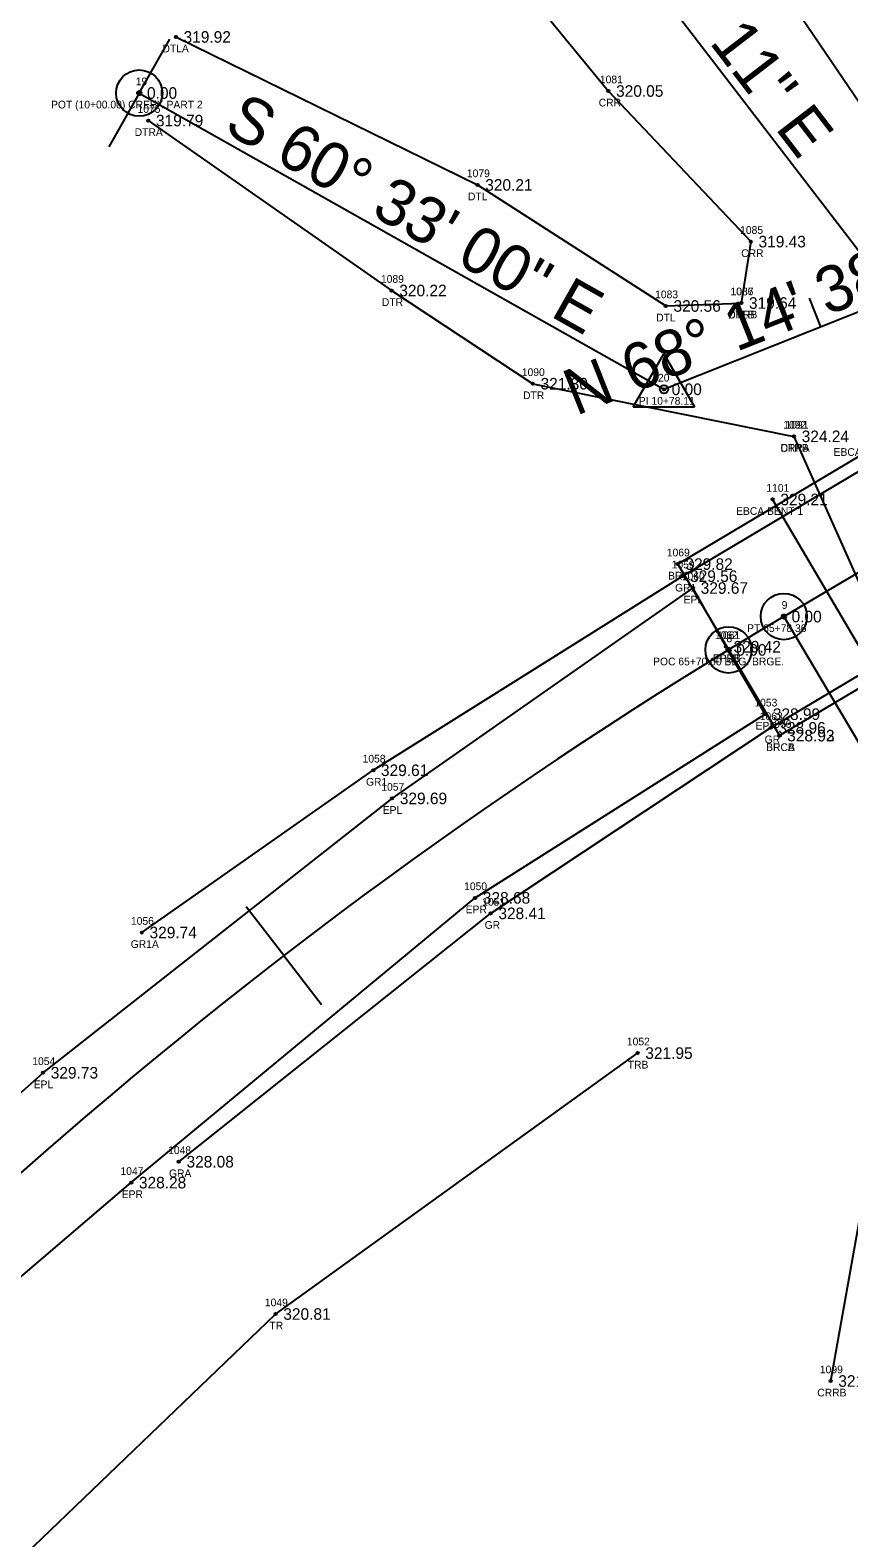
# Model space of a CAD drawing. Extents: x 2231119 to 2232595, y 1035731 to 1037094.
# Drawn here: x 2231451.3 to 2231557.4, y 1036309.5 to 1036504.9 of the extents above; entities that cross this region are included whole.
import ezdxf

# ---------------------------------------------------------------- set-up
doc = ezdxf.new("R2010")
doc.units = 0
for name, color, linetype in [('RD_EX_Bridge', 7, 'Continuous'), ('RD_EX_Bridge_txCode', 7, 'Continuous'), ('RD_EX_GuardRail', 7, 'Continuous'), ('RD_EX_GuardRail_txCode', 7, 'Continuous'), ('RD_EX_H2O', 7, 'Continuous'), ('RD_EX_H2O_txCode', 7, 'Continuous'), ('RD_EX_Road', 7, 'Continuous'), ('RD_EX_Road_txCode', 7, 'Continuous'), ('RD_EX_TX_Bridge_ELEV', 7, 'Continuous'), ('RD_EX_TX_GuardRail_ELEV', 7, 'Continuous'), ('RD_EX_TX_H2O_ELEV', 7, 'Continuous'), ('RD_EX_TX_Road_ELEV', 7, 'Continuous'), ('RD_EX_TX_VEG_ELEV', 7, 'Continuous'), ('RD_EX_VEG', 7, 'Continuous'), ('RD_EX_VEG_txCode', 7, 'Continuous'), ('RD_HC_Cl', 7, 'Continuous'), ('RD_HC_Data', 7, 'Continuous'), ('RD_HC_Data_Tic', 7, 'Continuous'), ('RD_HC_Survey_ELEV', 7, 'Continuous'), ('RD_HC_txCode', 7, 'Continuous'), ('RD_SMD_Locator', 7, 'Continuous')]:
    doc.layers.add(name, color=color, linetype=linetype)

msp = doc.modelspace()

# ---------------------------------------------------------------- linework, layer by layer
at = {"layer": 'RD_EX_Bridge'}
msp.add_line((2231547.53, 1036444.05), (2231561.63, 1036420.05), dxfattribs=at)
msp.add_lwpolyline([(2231548.42, 1036413.44), (2231612.8, 1036451.71), (2231599.65, 1036473.99), (2231535.22, 1036435.67), (2231548.41, 1036413.44)], dxfattribs=at)
at = {"layer": 'RD_EX_GuardRail'}
for points in [[(2231465.75, 1036387.92), (2231495.75, 1036408.95), (2231535.82, 1036434.11), (2231600.8, 1036472.75), (2231670.25, 1036516.04)], [(2231470.54, 1036358.21), (2231510.97, 1036390.4), (2231547.27, 1036414.45), (2231612.03, 1036453.05), (2231683.18, 1036493.79)]]:
    msp.add_lwpolyline(points, dxfattribs=at)
at = {"layer": 'RD_EX_H2O'}
for points in [[(2231513.64, 1036552.7), (2231545.27, 1036515.4), (2231572.49, 1036475.34)], [(2231494.58, 1036535.55), (2231526.23, 1036496.99), (2231544.7, 1036477.47), (2231543.46, 1036469.51)], [(2231470.16, 1036504), (2231509.27, 1036484.82), (2231533.67, 1036469.13), (2231543.46, 1036469.51)], [(2231466.58, 1036493.16), (2231498.13, 1036471.13), (2231516.44, 1036459.05), (2231550.29, 1036452.23)], [(2231550.29, 1036452.23), (2231565.49, 1036418.12), (2231564.98, 1036385.4), (2231555.04, 1036329.79)]]:
    msp.add_lwpolyline(points, dxfattribs=at)
at = {"layer": 'RD_EX_Road'}
for points in [[(2231158.42, 1035748.11), (2231188.37, 1035851.38), (2231216.59, 1035946.92), (2231244.77, 1036040.72), (2231278.59, 1036133.31), (2231299.55, 1036179.73), (2231323.11, 1036221.2), (2231350.7, 1036262.3), (2231381.59, 1036299.29), (2231415.97, 1036336.9), (2231452.94, 1036369.74), (2231498.19, 1036405.3), (2231537.2, 1036432.57), (2231541.46, 1036424.96)], [(2231176.43, 1035742.89), (2231206.61, 1035845.83), (2231234.19, 1035940.65), (2231261.92, 1036033.75), (2231294.68, 1036125.28), (2231316.11, 1036171.75), (2231338.19, 1036211.09), (2231363.83, 1036252.38), (2231394.08, 1036289.28), (2231427.67, 1036324.2), (2231464.37, 1036355.5), (2231508.96, 1036392.41), (2231546.55, 1036416.22), (2231541.46, 1036424.96)]]:
    msp.add_lwpolyline(points, dxfattribs=at)
at = {"layer": 'RD_EX_VEG'}
msp.add_lwpolyline([(2231211.01, 1035732.98), (2231244.87, 1035834.47), (2231267.87, 1035928.24), (2231283.13, 1036029.08), (2231316.25, 1036116.26), (2231338.15, 1036162.94), (2231357.98, 1036198.54), (2231413.07, 1036272.2), (2231445.22, 1036302.16), (2231483.09, 1036338.47), (2231530.02, 1036372.29)], dxfattribs=at)
at = {"layer": 'RD_HC_Cl'}
for p, q in [((2231548.98, 1036428.87), (2232281.06, 1036863.23)), ((2231504.54, 1036546.81), (2231563.32, 1036470.25)), ((2231465.42, 1036496.73), (2231533.44, 1036458.33)), ((2231533.44, 1036458.33), (2231563.32, 1036470.25))]:
    msp.add_line(p, q, dxfattribs=at)
msp.add_arc((2231880.38, 1035870.33), 649.46, 120.68197, 163.7355, dxfattribs=at)
at = {"layer": 'RD_HC_Data'}
for p, q in [((2231529.46, 1036456.04), (2231533.44, 1036462.92)), ((2231533.44, 1036462.92), (2231537.41, 1036456.04)), ((2231529.46, 1036456.04), (2231537.41, 1036456.04)), ((2231548.98, 1036428.87), (2231608.15, 1036329.15))]:
    msp.add_line(p, q, dxfattribs=at)
for centre, radius in [((2231465.42, 1036496.73), 3), ((2231465.42, 1036496.73), 0.282), ((2231533.44, 1036458.33), 0.529), ((2231548.98, 1036428.87), 3), ((2231541.82, 1036424.55), 3), ((2231548.98, 1036428.87), 0.282), ((2231541.82, 1036424.55), 0.282)]:
    msp.add_circle(centre, radius, dxfattribs=at)
at = {"layer": 'RD_HC_Data_Tic'}
for p, q in [((2231465.42, 1036496.73), (2231469.36, 1036503.7)), ((2231465.42, 1036496.73), (2231461.49, 1036489.76)), ((2231553.77, 1036466.44), (2231552.29, 1036470.16)), ((2231484.16, 1036384.92), (2231479.28, 1036391.26)), ((2231484.16, 1036384.92), (2231489.04, 1036378.58))]:
    msp.add_line(p, q, dxfattribs=at)
at = {"layer": 'RD_SMD_Locator'}
for centre in [(2231470.16, 1036504), (2231465.42, 1036496.73), (2231526.23, 1036496.99), (2231466.58, 1036493.16), (2231509.27, 1036484.82), (2231544.7, 1036477.47), (2231498.13, 1036471.13), (2231533.67, 1036469.13), (2231543.46, 1036469.51), (2231543.46, 1036469.51), (2231516.44, 1036459.05), (2231533.44, 1036458.33), (2231550.29, 1036452.23), (2231550.29, 1036452.23), (2231547.53, 1036444.05), (2231535.22, 1036435.67), (2231535.82, 1036434.11), (2231537.2, 1036432.57), (2231548.98, 1036428.87), (2231541.46, 1036424.96), (2231541.46, 1036424.96), (2231541.82, 1036424.55), (2231546.55, 1036416.22), (2231547.27, 1036414.45), (2231548.41, 1036413.44), (2231548.42, 1036413.44), (2231495.75, 1036408.95), (2231498.19, 1036405.3), (2231508.96, 1036392.41), (2231510.97, 1036390.4), (2231465.75, 1036387.92), (2231530.02, 1036372.29), (2231452.94, 1036369.74), (2231470.54, 1036358.21), (2231464.37, 1036355.5), (2231483.09, 1036338.47), (2231555.04, 1036329.79)]:
    msp.add_circle(centre, 0.15, dxfattribs=at)

# ---------------------------------------------------------------- texts
at = {"layer": 'RD_EX_Bridge_txCode'}
for s, p in [('EBCA BENT 2', (2231555.43, 1036449.7)), ('1101', (2231546.71, 1036445.05)), ('EBCA BENT 1', (2231542.79, 1036442.05)), ('1069', (2231533.81, 1036436.67)), ('BRC', (2231533.97, 1036433.67)), ('1070', (2231546.99, 1036414.44)), ('1066', (2231546.98, 1036414.44)), ('BRCA', (2231546.68, 1036411.44)), ('BRCB', (2231546.69, 1036411.44))]:
    msp.add_text(s, height=1, dxfattribs=at).set_placement(p)
at = {"layer": 'RD_EX_GuardRail_txCode'}
for s, p in [('1059', (2231534.44, 1036435.11)), ('GR1', (2231534.88, 1036432.11)), ('1063', (2231545.86, 1036415.45)), ('GR', (2231546.49, 1036412.45)), ('1058', (2231494.37, 1036409.95)), ('GR1', (2231494.81, 1036406.95)), ('1051', (2231509.87, 1036391.4)), ('1056', (2231464.34, 1036388.92)), ('GR', (2231510.19, 1036388.4)), ('GR1A', (2231464.31, 1036385.92)), ('1048', (2231469.16, 1036359.21)), ('GRA', (2231469.27, 1036356.21))]:
    msp.add_text(s, height=1, dxfattribs=at).set_placement(p)
at = {"layer": 'RD_EX_H2O_txCode'}
for s, p in [('DTLA', (2231468.42, 1036502)), ('1081', (2231525.13, 1036497.99)), ('CRR', (2231524.98, 1036494.99)), ('1075', (2231465.19, 1036494.16)), ('DTRA', (2231464.82, 1036491.16)), ('1079', (2231507.89, 1036485.82)), ('DTL', (2231508.03, 1036482.82)), ('1085', (2231543.31, 1036478.47)), ('CRR', (2231543.45, 1036475.47)), ('1089', (2231496.75, 1036472.13)), ('1083', (2231532.29, 1036470.13)), ('1086', (2231542.05, 1036470.51)), ('1087', (2231542.08, 1036470.51)), ('DTR', (2231496.87, 1036469.13)), ('CRRB', (2231541.74, 1036467.51)), ('DTLB', (2231541.75, 1036467.51)), ('DTL', (2231532.43, 1036467.13)), ('1090', (2231515.01, 1036460.05)), ('DTR', (2231515.17, 1036457.05)), ('1092', (2231548.91, 1036453.23)), ('1091', (2231549.19, 1036453.23)), ('CRRA', (2231548.55, 1036450.23)), ('DTRB', (2231548.55, 1036450.23)), ('1099', (2231553.65, 1036330.79)), ('CRRB', (2231553.31, 1036327.79))]:
    msp.add_text(s, height=1, dxfattribs=at).set_placement(p)
at = {"layer": 'RD_EX_Road_txCode'}
for s, p in [('1060', (2231535.75, 1036433.57)), ('EPL', (2231535.99, 1036430.57)), ('1062', (2231540.05, 1036425.96)), ('1061', (2231540.33, 1036425.96)), ('EPRB', (2231539.76, 1036422.96)), ('EPLB', (2231539.78, 1036422.96)), ('1053', (2231545.16, 1036417.22)), ('EPR', (2231545.32, 1036414.22)), ('1057', (2231496.8, 1036406.3)), ('EPL', (2231496.98, 1036403.3)), ('1050', (2231507.53, 1036393.41)), ('EPR', (2231507.73, 1036390.41)), ('1054', (2231451.55, 1036370.74)), ('EPL', (2231451.73, 1036367.74)), ('1047', (2231462.98, 1036356.5)), ('EPR', (2231463.14, 1036353.5))]:
    msp.add_text(s, height=1, dxfattribs=at).set_placement(p)
at = {"layer": 'RD_EX_TX_Bridge_ELEV'}
for s, p in [('329.21', (2231548.53, 1036443.3)), ('329.82', (2231536.22, 1036434.92)), ('328.93', (2231549.42, 1036412.69)), ('328.92', (2231549.41, 1036412.69))]:
    msp.add_text(s, height=1.5, dxfattribs=at).set_placement(p)
at = {"layer": 'RD_EX_TX_GuardRail_ELEV'}
for s, p in [('329.56', (2231536.82, 1036433.36)), ('328.96', (2231548.27, 1036413.7)), ('329.61', (2231496.75, 1036408.2)), ('328.41', (2231511.97, 1036389.65)), ('329.74', (2231466.75, 1036387.17)), ('328.08', (2231471.54, 1036357.46))]:
    msp.add_text(s, height=1.5, dxfattribs=at).set_placement(p)
at = {"layer": 'RD_EX_TX_H2O_ELEV'}
for s, p in [('319.92', (2231471.16, 1036503.25)), ('320.05', (2231527.23, 1036496.24)), ('319.79', (2231467.58, 1036492.41)), ('320.21', (2231510.27, 1036484.07)), ('319.43', (2231545.7, 1036476.72)), ('320.22', (2231499.13, 1036470.38)), ('319.64', (2231544.46, 1036468.76)), ('319.64', (2231544.46, 1036468.76)), ('320.56', (2231534.67, 1036468.38)), ('321.30', (2231517.44, 1036458.3)), ('324.24', (2231551.29, 1036451.48)), ('324.24', (2231551.29, 1036451.48)), ('321.00', (2231556.04, 1036329.04))]:
    msp.add_text(s, height=1.5, dxfattribs=at).set_placement(p)
at = {"layer": 'RD_EX_TX_Road_ELEV'}
for s, p in [('329.67', (2231538.2, 1036431.82)), ('329.42', (2231542.46, 1036424.21)), ('329.42', (2231542.46, 1036424.21)), ('328.99', (2231547.55, 1036415.47)), ('329.69', (2231499.19, 1036404.55)), ('328.68', (2231509.96, 1036391.66)), ('329.73', (2231453.94, 1036368.99)), ('328.28', (2231465.37, 1036354.75))]:
    msp.add_text(s, height=1.5, dxfattribs=at).set_placement(p)
at = {"layer": 'RD_EX_TX_VEG_ELEV'}
for s, p in [('321.95', (2231531.02, 1036371.54)), ('320.81', (2231484.09, 1036337.72))]:
    msp.add_text(s, height=1.5, dxfattribs=at).set_placement(p)
at = {"layer": 'RD_EX_VEG_txCode'}
for s, p in [('1052', (2231528.63, 1036373.29)), ('TRB', (2231528.75, 1036370.29)), ('1049', (2231481.7, 1036339.47)), ('TR', (2231482.29, 1036336.47))]:
    msp.add_text(s, height=1, dxfattribs=at).set_placement(p)
at = {"layer": 'RD_HC_Data'}
for s, rotation, p in [('S 37%%d 31\' 11" E', 307.5197, (2231518.13, 1036530.75)), ('S 60%%d 33\' 00" E', 330.55, (2231476.2, 1036491.79)), ('N 68%%d 14\' 38" E', 21.756, (2231522.02, 1036454.85))]:
    msp.add_text(s, height=6, rotation=rotation, dxfattribs=at).set_placement(p)
at = {"layer": 'RD_HC_Survey_ELEV'}
for p in [(2231466.42, 1036495.98), (2231534.44, 1036457.58), (2231549.98, 1036428.12), (2231542.82, 1036423.8)]:
    msp.add_text('0.00', height=1.5, dxfattribs=at).set_placement(p)
at = {"layer": 'RD_HC_txCode'}
for s, p in [('19', (2231464.97, 1036497.73)), ('POT (10+00.00) CREEK PART 2', (2231453.98, 1036494.73)), ('20', (2231532.66, 1036459.33)), ('PI 10+78.11', (2231530.18, 1036456.33)), ('9', (2231548.7, 1036429.87)), ('PT 65+78.36', (2231544.22, 1036426.87)), ('8', (2231541.54, 1036425.55)), ('POC 65+70.00 BEG. BRGE.', (2231532.03, 1036422.55))]:
    msp.add_text(s, height=1, dxfattribs=at).set_placement(p)

doc.saveas('drawing.dxf')
